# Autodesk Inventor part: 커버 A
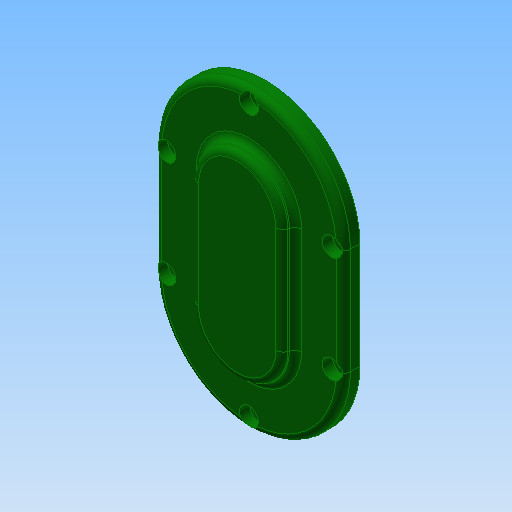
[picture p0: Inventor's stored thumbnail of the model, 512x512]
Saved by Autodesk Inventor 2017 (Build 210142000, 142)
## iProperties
Created: 2020-04
Part Number: 커버 A
Material: 알루미늄 6061
Document SubType Name: Modeling
Designer: mduedu
Density: 2.71 g/cm^3
Mass: 189.426 g
Surface Area: 209.668 cm^2
Volume: 69.8987 cm^3
Appearance: 진녹색
Author: mduedu
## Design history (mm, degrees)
sketch "스케치1"
  geometry: L1 (-40, 0)-(-40, -45); L2 (40, 0)-(40, -45); A1 r 40 centre (0, 0) between (40, 0) and (-40, 0); A2 r 40 centre (0, -45) between (-40, -45) and (40, -45); 1 further point
  constraints: 4 end point, 4 point on circle, 4 tangent, 2 centre point, 1 coincident, 1 equal radius, 1 vertical alignment
  dimensions: "d0" = 80 diameter of A1; "d31" = 45 distance of point (0, 0) A2.centre
extrude "돌출1" new body sketch "스케치1" distance "d1" = 7; taper "d2" = 0 deg
fillet "모깎기2" dims "d7" = 3
sketch "스케치4"
  geometry: L1 (30, 0)-(30, -45); L2 (-30, 0)-(-30, -45); A1 r 30 centre (0, 0) between (30, 0) and (-30, 0); A2 r 30 centre (0, -45) between (-30, -45) and (30, -45); 1 further point
  constraints: 4 end point, 4 point on circle, 4 tangent, 2 centre point, 1 coincident, 1 equal radius, 1 vertical alignment
  dimensions: "d19" = 60 diameter of A1; "d38" = 45 distance of point (0, 0) A2.centre
extrude "돌출3" join sketch "스케치4" distance "d20" = 4; taper "d21" = 0 deg
sketch "스케치7"
  geometry: L1 (-20, 0)-(-20, -45); L2 (20, 0)-(20, -45); A1 r 20 centre (0, 0) between (20, 0) and (-20, 0); A2 r 20 centre (0, -45) between (-20, -45) and (20, -45); 1 further point
  constraints: 4 end point, 4 point on circle, 4 tangent, 2 centre point, 1 coincident, 1 equal radius, 1 vertical alignment
  dimensions: "d45" = 40 diameter of A1; "d47" = 45 distance of point (0, 0) A2.centre
extrude "돌출5" join sketch "스케치7" distance "d48" = 5; taper "d49" = -15 deg
fillet "모깎기4" dims "d50" = 3
chamfer "모따기2" distance "d58" = 1; stored, may be unused: second distance "d59" = 2, angle "d60" = 45 deg
sketch "스케치6"
  geometry: L1 (0, 7)-(37, 7) reference; L2 (0, -4)-(30, -4) reference; L3 (0, -4)-(0, 8); L4 (0, 8)-(8, 8); L5 (11, 5)-(11, 5); L6 (11, 5)-(16, 5); L7 (16, 5)-(16, -4); L8 (-45, -4)-(-45, 8); L9 (-45, 8)-(-37, 8); L10 (-34, 5)-(-34, 4); L11 (-34, 4)-(-31, 4); L12 (-31, 4)-(-31, -4); L13 (-31, -4)-(-45, -4); A1 r 3 centre (8, 5) between (11, 5) and (8, 8); A2 r 3 centre (-37, 5) between (-34, 5) and (-37, 8); 3 further points
  constraints: 22 end point, 5 parallel, 5 point on line, 4 perpendicular, 4 point on circle, 4 tangent, 2 centre point, 2 horizontal alignment, 1 horizontal, 1 vertical
  dimensions: "d39" = 32 diameter of L7 L3; "d41" = 3 distance of point (11, 8) L5.end; "d42" = 9 distance of L6.end L7.end; "d43" = 22 diameter of L5 L3; "d44" = 3 radius of A1; "d51" = 8 distance of L11.end L12.end; "d52" = 45 distance of L2.start L8.start; "d53" = 28 diameter of L12 L8; "d54" = 22 diameter of L10 L8; "d55" = 3 radius of A2
revolve "회전1" stored, may be unused: angle "d56" = 90 deg
revolve "회전2" stored, may be unused: angle "d57" = 90 deg
sketch "스케치3"
  geometry: A1 r 35 centre (0, 0) between (0, 35) and (-35, 0); A2 r 35 centre (0, -45) between (-35, -45) and (0, -80); 3 further points
  constraints: 6 point on circle, 5 vertical alignment, 2 centre point, 2 horizontal alignment, 1 coincident, 1 equal radius
  dimensions: "d8" = 70 diameter of A1; "d69" = 45 distance of point (0, 0) A2.centre
hole "구멍1" sketch "스케치3" at (0, 35), (-35, 0), (-35, -45), (0, -80), (35, -45), (35, 0) diameter "d9" = 4.5; stored, may be unused: countersink angle "d13" = 90 deg, drill point angle "d15" = 118 deg; dims "d10" = 6, "d11" = 8, "d12" = 4.4, "d14" = 8
fillet "모깎기5" dims "d70" = 0.3
chamfer "모따기3" distance "d71" = 1; stored, may be unused: second distance "d72" = 2, angle "d73" = 45 deg
node "솔리드1"
